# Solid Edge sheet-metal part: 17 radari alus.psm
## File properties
Author: Henri
Template: Normal.psm
Last saved by: Henri
Revision: 5
Application: Solid Edge
Accuracy: 0,990
Material Thickness: 2,50 mm
Bend Radius: 1,00 mm
Relief Width: 1,00 mm
Relief Length: 0,00 mm
Neutral Factor: 0,330
Minimum Arc Length: 0,10 mm
Deviational Tolerance: 0,10 mm
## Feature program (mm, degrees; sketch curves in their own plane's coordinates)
base tab "unnamed BaseTab 1"
flange "Flange_3"
jog tab "JogTab_5"  OffsetDistance = 5 mm
flange "Flange_5"
jog tab "JogTab_6"  OffsetDistance = 5 mm
louver "Louver_3"  LouverDepth = 7.5 mm; LouverHeight = 4 mm
bead "unnamed Bead 1"
dimple "Dimple_2"
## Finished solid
Body 1: solid body, 66 faces, 170 edges, 110 vertices.
  Faces by surface: plane 28, cylinder 26, cone 4, sphere 4, torus 4
  Edges by curve: line 104, circle 58, ellipse 8
Bounding box of the edges (mm; curved faces can reach further): 57.125 x 35.000 x 22.500, from (-28.125, -17.5, -12.5) to (29, 17.5, 10).
Cylindrical faces by radius (mm): R1 x6, R2.5 x12, R3.5 x6, R6.5313 x1, R9.0313 x1
Conical faces (half-angle, radius in mm at the cone's reference point): 15 deg R0.7535 x1, 15 deg R1.5908 x1, 15 deg R3.1683 x1, 15 deg R4.0057 x1
Toroidal faces (ring radius, tube radius in mm): R1.25 r2.5 x2, R4.0057 r2.5 x2
Spherical faces by radius (mm): R6.5313 x2, R9.0313 x2
Planar faces by outward normal: +x 5, +y 1, +z 5, -x 5, -y 1, -z 7, oblique 4
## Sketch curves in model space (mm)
line (12.5, -12.5, 0) -> (12.5, 12.5, 0)
line (12.5, 12.5, 0) -> (-12.5, 12.5, 0)
line (-12.5, 12.5, 0) -> (-12.5, -12.5, 0)
line (-12.5, -12.5, 0) -> (12.5, -12.5, 0)
line (25, 17.5, 0) -> (25, -17.5, 0)
line (25, -17.5, 0) -> (-25, -17.5, 0)
line (-25, -17.5, 0) -> (-25, 17.5, 0)
line (-25, 17.5, 0) -> (25, 17.5, 0)
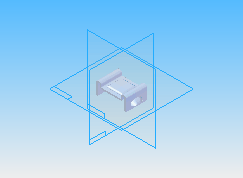
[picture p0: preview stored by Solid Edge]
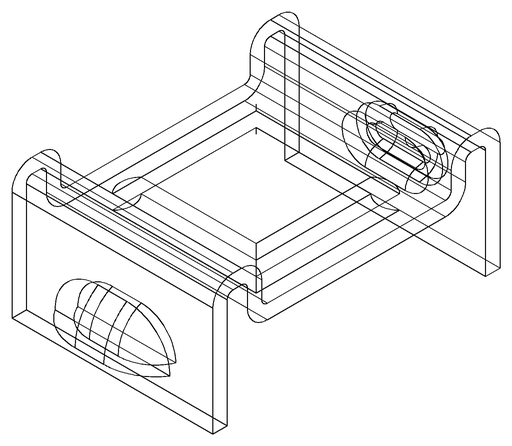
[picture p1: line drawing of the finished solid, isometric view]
